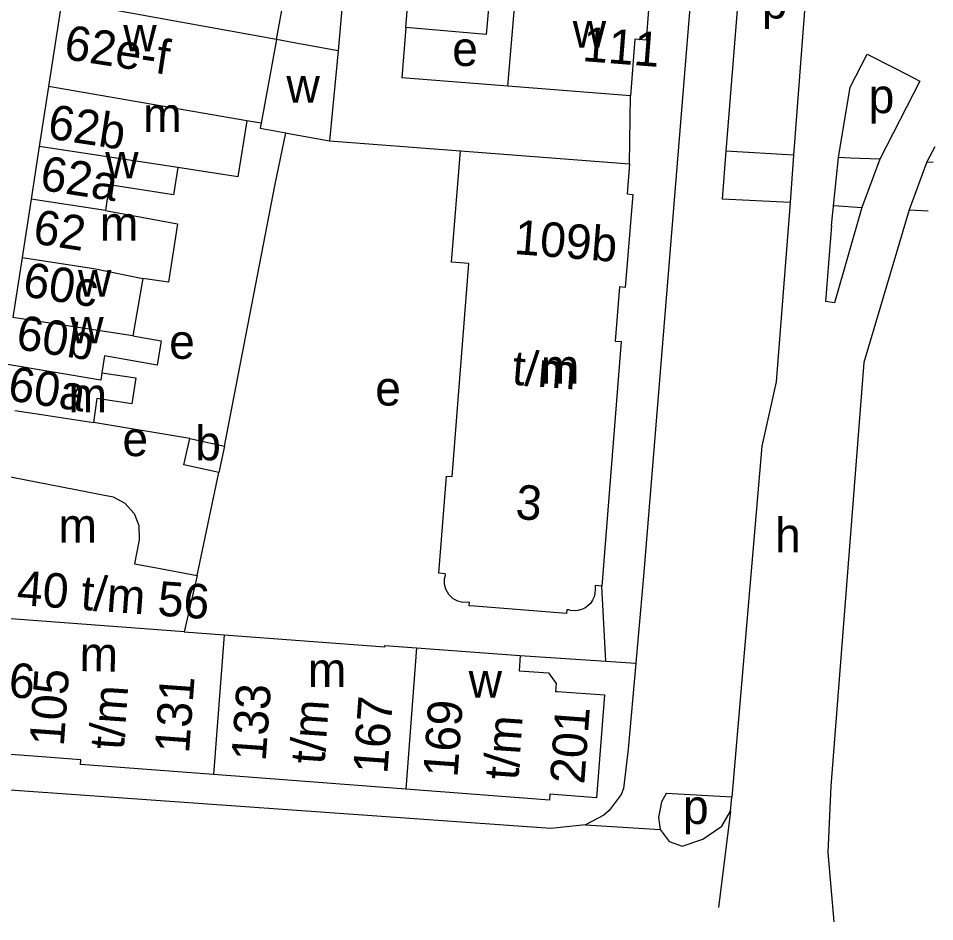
# Model space of a CAD drawing. Extents: x 159902 to 161769, y 383692 to 384875.
# Drawn here: x 161124 to 161230.2, y 384025.6 to 384130.3 of the extents above; entities that cross this region are included whole.
import ezdxf

# ---------------------------------------------------------------- set-up
doc = ezdxf.new("R2010")
doc.units = 0
for name, color, linetype in [('BLT_Basislijn', 7, 'Continuous'), ('BLT_Bebouwing', 7, 'Continuous'), ('BLT_Centroide', 7, 'Continuous'), ('BLT_Huisnummer', 7, 'Continuous'), ('BLT_Huisnummer_reeks', 7, 'Continuous'), ('BLT_Onderverdeling_panden', 7, 'Continuous'), ('BLT_Vlakafsluiter', 7, 'Continuous')]:
    doc.layers.add(name, color=color, linetype=linetype)

msp = doc.modelspace()

# ---------------------------------------------------------------- linework, layer by layer
at = {"layer": 'BLT_Basislijn'}
for p, q in [((161216.28, 384146.98), (161213.8, 384114.43)), ((161208.49, 384146.42), (161205.98, 384114.9)), ((161168.89, 384129.2), (161168.42, 384123.37)), ((161226.97, 384123.75), (161228.45, 384122.99)), ((161180.71, 384122.41), (161168.42, 384123.37)), ((161194.79, 384113.41), (161194.92, 384121.29)), ((161152.13, 384118.12), (161150.49, 384118.4)), ((161153.74, 384111.07), (161154.97, 384117.01)), ((161160.04, 384116.08), (161175.22, 384114.93)), ((161205.98, 384114.9), (161205.53, 384109.32)), ((161213.8, 384114.43), (161205.98, 384114.9)), ((161213.8, 384114.43), (161213.42, 384108.95)), ((161218.2, 384106.28), (161219.03, 384114.15)), ((161220.39, 384114.09), (161219.03, 384114.15)), ((161223.79, 384113.95), (161220.39, 384114.09)), ((161229.25, 384113.63), (161227.2, 384108.09)), ((161229.25, 384113.63), (161229.97, 384113.61)), ((161147.89, 384080.73), (161153.74, 384111.07)), ((161213.42, 384108.95), (161205.53, 384109.32)), ((161213.42, 384108.95), (161211.78, 384088.18)), ((161218.51, 384108.58), (161221.73, 384108.34)), ((161227.2, 384108.09), (161229.39, 384107.99)), ((161218.2, 384106.28), (161217.51, 384097.47)), ((161143.86, 384081.61), (161132.69, 384083.47)), ((161144.73, 384065.74), (161147.22, 384077.65)), ((161197.23, 384075.56), (161196.41, 384065.64)), ((161192.07, 384055.81), (161191.59, 384064.5)), ((161182.14, 384056.45), (161192.07, 384055.81)), ((161192.07, 384055.81), (161195.54, 384055.58)), ((161206.51, 384038.42), (161206.67, 384040.05))]:
    msp.add_line(p, q, dxfattribs=at)
for points in [[(161206.86, 384290.77), (161210.33, 384289.66), (161212.25, 384287.97), (161213.36, 384285.84), (161213.55, 384284.75), (161213.59, 384280.48), (161205.71, 384179.4), (161197.23, 384075.56)], [(161219.03, 384114.15), (161220.37, 384122.29), (161222.34, 384126.13), (161225.39, 384124.56), (161226.97, 384123.75)], [(161228.45, 384122.99), (161223.79, 384113.95)], [(161230.16, 384115.39), (161229.25, 384113.63)], [(161223.79, 384113.95), (161221.73, 384108.34)], [(161221.73, 384108.34), (161218.54, 384097.33), (161217.51, 384097.47)], [(161227.2, 384108.09), (161221.97, 384090.39), (161218.12, 384041.34)], [(161211.78, 384088.18), (161210.14, 384080.72), (161207.32, 384047.74), (161206.67, 384040.05)], [(161196.41, 384065.64), (161195.62, 384056.47), (161195.54, 384055.58)], [(161195.54, 384055.58), (161194.65, 384045.61), (161194.09, 384041.06), (161193.84, 384040.37), (161192.46, 384038.52), (161191.85, 384037.98), (161189.71, 384036.84)], [(161189.71, 384036.84), (161185.7, 384036.44), (161119.18, 384041.13)], [(161218.12, 384041.34), (161217.79, 384033.65), (161218.46, 384025.63)], [(161206.67, 384040.05), (161199.06, 384040.47), (161198.5, 384039.5), (161198.17, 384037.71), (161198.37, 384036.31)], [(161199.4, 384034.92), (161200.92, 384034.39), (161203.29, 384035.19), (161205.51, 384036.69), (161206.51, 384038.42)], [(161198.37, 384036.31), (161199.4, 384034.92)]]:
    msp.add_lwpolyline(points, dxfattribs=at)
at = {"layer": 'BLT_Bebouwing'}
for p, q in [((161162.62, 384144.39), (161161.06, 384126.51)), ((161129.03, 384132.33), (161127.5, 384122.36)), ((161161.06, 384126.51), (161160.04, 384116.08)), ((161127.5, 384122.36), (161126.43, 384115.44)), ((161150.49, 384118.4), (161149.43, 384111.91)), ((161126.43, 384115.44), (161125.5, 384109.33)), ((161175.22, 384114.93), (161194.79, 384113.41)), ((161125.5, 384109.33), (161124.43, 384102.58)), ((161124.43, 384102.58), (161123.36, 384095.61)), ((161138.41, 384100.15), (161137.26, 384093.48)), ((161143.86, 384081.61), (161147.89, 384080.73)), ((161147.89, 384080.73), (161147.22, 384077.65)), ((161191.59, 384064.5), (161190.82, 384064.57)), ((161126.22, 384044.76), (161120.59, 384045.18))]:
    msp.add_line(p, q, dxfattribs=at)
for points in [[(161168.89, 384129.2), (161170.58, 384150.24)], [(161153.89, 384127.82), (161157.13, 384145.39)], [(161181.83, 384135.52), (161178.86, 384135.76), (161178.19, 384128.38), (161168.89, 384129.2)], [(161153.89, 384127.82), (161134.46, 384131.35), (161129.03, 384132.33)], [(161180.71, 384122.41), (161181.57, 384132.47)], [(161197, 384131.26), (161196.73, 384127.74), (161195.44, 384127.85), (161194.92, 384121.29)], [(161194.92, 384121.29), (161180.71, 384122.41)], [(161152.13, 384118.12), (161152.02, 384117.54), (161154.97, 384117.01)], [(161154.97, 384117.01), (161155.12, 384116.98), (161160.04, 384116.08)], [(161173.46, 384065.93), (161172.71, 384065.99), (161173.59, 384077.25), (161174.27, 384077.2), (161176.2, 384101.88), (161174.19, 384102.04), (161175.22, 384114.93)], [(161142.46, 384112.98), (161141.97, 384109.83), (161134.54, 384110.97), (161134.08, 384108.01)], [(161149.43, 384111.91), (161142.46, 384112.98)], [(161194.79, 384113.41), (161194.53, 384109.93), (161195.19, 384109.87), (161194.32, 384099.1), (161193.66, 384099.16), (161193.15, 384092.87), (161193.82, 384092.82), (161191.59, 384064.5)], [(161134.08, 384108.01), (161142.45, 384106.46), (161141.41, 384099.69), (161138.41, 384100.15)], [(161137.26, 384093.48), (161140.56, 384092.91), (161140.08, 384090.11), (161133.99, 384091.17), (161133.69, 384089.22)], [(161133.69, 384089.22), (161137.61, 384088.62), (161137.15, 384085.63), (161133.11, 384086.25), (161132.69, 384083.47)], [(161123.58, 384084.86), (161126.7, 384084.39), (161132.69, 384083.47)], [(161147.22, 384077.65), (161143.18, 384078.54), (161143.86, 384081.61)], [(161121.87, 384077.38), (161134.98, 384074.83), (161136.34, 384074.1), (161137.4, 384072.9), (161137.94, 384071.53), (161137.98, 384069.86), (161137.44, 384067.08), (161139.81, 384066.64), (161144.73, 384065.74)], [(161144.73, 384065.74), (161143.21, 384059.21)], [(161173.46, 384065.93), (161173.44, 384065.72), (161173.35, 384065.31), (161173.35, 384064.78), (161173.48, 384064.19), (161173.82, 384063.58), (161174.33, 384063.08), (161174.86, 384062.8), (161175.49, 384062.65), (161176.06, 384062.68), (161176.27, 384062.66)], [(161190.82, 384064.57), (161190.81, 384064.36), (161190.83, 384064.09), (161190.8, 384063.66), (161190.7, 384063.25), (161190.52, 384062.86), (161190.28, 384062.5), (161189.98, 384062.2), (161189.62, 384061.96), (161189.23, 384061.78), (161188.82, 384061.67), (161188.39, 384061.64), (161187.96, 384061.69), (161187.76, 384061.74), (161187.54, 384061.76)], [(161187.54, 384061.76), (161187.51, 384061.32), (161176.86, 384062.16), (161176.23, 384062.22), (161176.27, 384062.66)], [(161143.21, 384059.21), (161147.84, 384058.86)], [(161147.84, 384058.86), (161166.45, 384057.45), (161166.46, 384057.63), (161170.13, 384057.36)], [(161170.13, 384057.36), (161182.14, 384056.45)], [(161182.14, 384056.45), (161182.01, 384054.69)], [(161182.01, 384054.69), (161185.43, 384054.44)], [(161185.43, 384054.44), (161186.31, 384053.22), (161186.25, 384052.31), (161186.47, 384052.3)], [(161186.47, 384052.3), (161191.89, 384051.89), (161190.99, 384039.99), (161185.59, 384040.39)], [(161146.61, 384042.66), (161131.21, 384043.83), (161131.25, 384044.38), (161126.22, 384044.76)], [(161168.89, 384040.98), (161146.61, 384042.66)], [(161185.59, 384040.39), (161185.54, 384039.72), (161168.89, 384040.98)]]:
    msp.add_lwpolyline(points, dxfattribs=at)
at = {"layer": 'BLT_Onderverdeling_panden'}
for p, q in [((161150.49, 384118.4), (161127.5, 384122.36)), ((161142.46, 384112.98), (161126.43, 384115.44)), ((161134.08, 384108.01), (161125.5, 384109.33)), ((161124.43, 384102.58), (161132.74, 384101.3)), ((161132.74, 384101.3), (161138.41, 384100.15)), ((161137.26, 384093.48), (161123.36, 384095.61)), ((161143.21, 384059.21), (161118.18, 384061.1)), ((161147.84, 384058.86), (161146.61, 384042.66)), ((161170.13, 384057.36), (161168.89, 384040.98))]:
    msp.add_line(p, q, dxfattribs=at)
for points in [[(161153.89, 384127.82), (161152.13, 384118.12)], [(161161.06, 384126.51), (161156.14, 384127.41), (161153.89, 384127.82)], [(161133.69, 384089.22), (161133.57, 384088.37), (161122.53, 384090.2)]]:
    msp.add_lwpolyline(points, dxfattribs=at)
at = {"layer": 'BLT_Vlakafsluiter'}
for p, q in [((161206.51, 384038.42), (161205.1, 384027.27)), ((161189.71, 384036.84), (161198.37, 384036.31))]:
    msp.add_line(p, q, dxfattribs=at)

# ---------------------------------------------------------------- texts
at = {"layer": 'BLT_Centroide'}
for s, p in [('p', (161210.13, 384130.25)), ('w', (161188.23, 384126.88)), ('w', (161136.16, 384126.44)), ('e', (161174.27, 384124.75)), ('w', (161155.06, 384120.5)), ('p', (161222.51, 384119.29)), ('m', (161138.46, 384117.12)), ('w', (161134.06, 384111.72)), ('m', (161133.45, 384104.5)), ('w', (161130.91, 384098.03)), ('w', (161130.02, 384092.62)), ('e', (161141.47, 384090.83)), ('m', (161184.53, 384087.94)), ('e', (161165.35, 384085.42)), ('m', (161129.82, 384084.64)), ('b', (161144.49, 384079.08)), ('e', (161136.06, 384079.56)), ('m', (161128.65, 384069.52)), ('h', (161211.67, 384068.42)), ('m', (161157.54, 384052.81)), ('w', (161176.17, 384051.59)), ('p', (161201, 384036.95))]:
    msp.add_text(s, height=4, dxfattribs=at).set_placement(p)
msp.add_text('m', height=4, rotation=359, dxfattribs=at).set_placement((161131.06, 384054.66))
at = {"layer": 'BLT_Huisnummer'}
for s, rotation, p in [('62b', 351.2791, (161127.26, 384116.39)), ('62a', 351.2814, (161126.38, 384110.43)), ('62', 351.2926, (161125.57, 384104.22)), ('60c', 351.2752, (161124.38, 384098.1)), ('60b', 351.2856, (161123.61, 384091.98)), ('60a', 351.2872, (161122.65, 384086.06))]:
    msp.add_text(s, height=4, rotation=rotation, dxfattribs=at).set_placement(p)
at = {"layer": 'BLT_Huisnummer_reeks'}
for s, rotation, p in [('62e-f', 351.2883, (161129.15, 384125.58)), ('111', 355.5074, (161189.26, 384125.33)), ('109b', 355.5085, (161181.36, 384102.98)), ('t/m', 355.5085, (161181.11, 384087.85)), ('3', 355.5085, (161181.52, 384072.3)), ('40 t/m 56', 355.6763, (161123.74, 384062.34)), ('36', 355.6763, (161119.83, 384051.88)), ('105', 85.8968, (161129.26, 384045.88)), ('131', 85.796, (161143.77, 384045.06)), ('t/m', 85.9955, (161136.21, 384045.47)), ('133', 85.8968, (161152.65, 384044.14)), ('167', 85.796, (161166.75, 384042.68)), ('t/m', 85.9955, (161159.47, 384043.8)), ('169', 85.8968, (161174.87, 384042.26)), ('t/m', 85.9955, (161181.92, 384041.97)), ('201', 85.796, (161189.56, 384041.49))]:
    msp.add_text(s, height=4, rotation=rotation, dxfattribs=at).set_placement(p)

doc.saveas('drawing.dxf')
